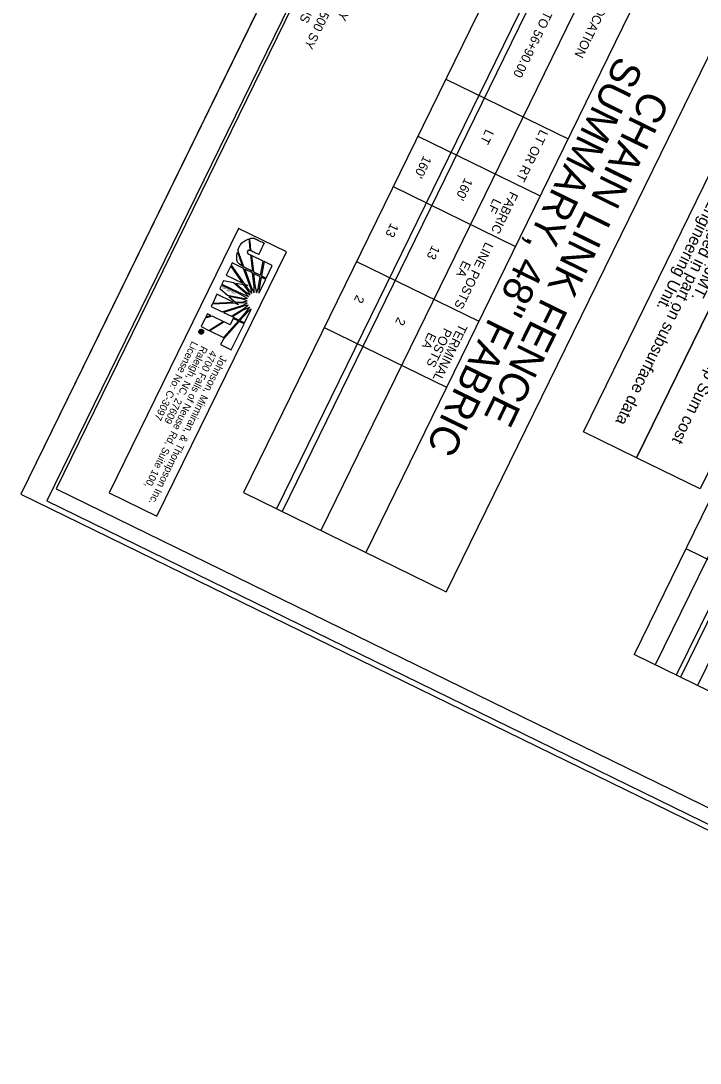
# Model space of a CAD drawing. Extents: x 1527431 to 1570373, y 611106 to 634616.
# Drawn here: x 1527567.8 to 1527683.1, y 634217 to 634394 of the extents above; entities that cross this region are included whole.
import ezdxf

# ---------------------------------------------------------------- set-up
doc = ezdxf.new("R2010")
doc.units = 0
for name, color, linetype in [('Sheet Cutting Line CELL', 7, 'Continuous'), ('Sheet Plot Border Inside CELL', 7, 'Continuous'), ('Sheet Plot Border Outside CELL', 7, 'Continuous'), ('Sheet Summary Earthwork CELL', 7, 'Continuous')]:
    doc.layers.add(name, color=color, linetype=linetype)

msp = doc.modelspace()

# ---------------------------------------------------------------- linework, layer by layer
at = {"layer": 'Sheet Cutting Line CELL'}
msp.add_line((1527715.73, 634616.24), (1527567.76, 634313.68), dxfattribs=at)
at = {"layer": 'Sheet Plot Border Inside CELL'}
msp.add_lwpolyline([(1527761.75, 634219.81), (1527908.19, 634519.22), (1527718.63, 634611.93), (1527572.19, 634312.52)], close=True, dxfattribs=at)
at = {"layer": 'Sheet Plot Border Outside CELL'}
msp.add_lwpolyline([(1527765.39, 634217.03), (1527913.36, 634519.58), (1527715.73, 634616.24), (1527567.76, 634313.68)], close=True, dxfattribs=at)
at = {"layer": 'Sheet Summary Earthwork CELL'}
for p, q in [((1527655.39, 634415.88), (1527605.53, 634313.93)), ((1527661.01, 634413.13), (1527611.14, 634311.18)), ((1527661.96, 634412.66), (1527612.1, 634310.71)), ((1527668.52, 634409.46), (1527618.66, 634307.51)), ((1527676.16, 634405.72), (1527626.3, 634303.77)), ((1527689.83, 634399.03), (1527639.97, 634297.08)), ((1527721.7, 634388.4), (1527671.84, 634286.45)), ((1527725.29, 634386.64), (1527675.43, 634284.69)), ((1527639.87, 634384.15), (1527660.64, 634373.99)), ((1527728.89, 634384.88), (1527679.02, 634282.93)), ((1527729.58, 634384.55), (1527679.72, 634282.59)), ((1527732.48, 634383.13), (1527682.62, 634281.18)), ((1527635.13, 634374.45), (1527655.9, 634364.29)), ((1527630.94, 634365.88), (1527651.71, 634355.72)), ((1527606.92, 634354.18), (1527607.23, 634351.42)), ((1527608.89, 634353.22), (1527606.92, 634354.18)), ((1527603.39, 634352.4), (1527602.62, 634350.83)), ((1527605.43, 634349.47), (1527603.39, 634352.4)), ((1527603.64, 634352.91), (1527603.47, 634352.56)), ((1527603.47, 634352.56), (1527605.73, 634349.33)), ((1527605.55, 634351.98), (1527603.64, 634352.91)), ((1527606.83, 634348.49), (1527605.55, 634351.98)), ((1527608.45, 634350.83), (1527608.89, 634353.22)), ((1527609.05, 634353.14), (1527608.6, 634350.75)), ((1527610.44, 634352.46), (1527609.05, 634353.14)), ((1527609.41, 634350.36), (1527610.44, 634352.46)), ((1527624.73, 634353.18), (1527645.5, 634343.02)), ((1527602.62, 634350.83), (1527605.43, 634349.47)), ((1527607.08, 634351.23), (1527605.77, 634351.87)), ((1527605.77, 634351.87), (1527606.99, 634348.52)), ((1527607.35, 634348.84), (1527607.08, 634351.23)), ((1527607.23, 634351.42), (1527608.45, 634350.83)), ((1527608.4, 634350.58), (1527607.26, 634351.14)), ((1527607.26, 634351.14), (1527607.49, 634349.07)), ((1527608.03, 634348.58), (1527608.4, 634350.58)), ((1527608.56, 634350.5), (1527608.19, 634348.5)), ((1527609.32, 634350.13), (1527608.56, 634350.5)), ((1527608.6, 634350.75), (1527609.41, 634350.36)), ((1527601.81, 634349.15), (1527601.53, 634348.56)), ((1527601.53, 634348.56), (1527602.81, 634347.43)), ((1527604.62, 634347.78), (1527601.81, 634349.15)), ((1527602.17, 634349.87), (1527601.89, 634349.3)), ((1527601.89, 634349.3), (1527604.69, 634347.93)), ((1527603.88, 634349.53), (1527602.17, 634349.87)), ((1527605.86, 634347.82), (1527603.88, 634349.53)), ((1527605.63, 634349.18), (1527604.2, 634349.45)), ((1527604.2, 634349.45), (1527606.04, 634347.89)), ((1527606.33, 634348.19), (1527605.63, 634349.18)), ((1527605.73, 634349.33), (1527606.29, 634349.06)), ((1527606.29, 634349.06), (1527605.86, 634349.14)), ((1527605.86, 634349.14), (1527606.44, 634348.31)), ((1527606.99, 634347.72), (1527606.83, 634348.49)), ((1527606.99, 634348.52), (1527607.36, 634347.84)), ((1527607.36, 634347.84), (1527607.35, 634348.84)), ((1527607.49, 634349.07), (1527607.78, 634347.85)), ((1527607.78, 634347.85), (1527608.03, 634348.58)), ((1527608.16, 634347.77), (1527609.32, 634350.13)), ((1527608.19, 634348.5), (1527608.16, 634347.77)), ((1527601.05, 634347.59), (1527600.32, 634346.08)), ((1527603.79, 634346.25), (1527601.05, 634347.59)), ((1527602.81, 634347.43), (1527605.42, 634346.91)), ((1527605.45, 634346.74), (1527603.06, 634347.23)), ((1527603.06, 634347.23), (1527604.17, 634346.27)), ((1527606.23, 634346.86), (1527604.62, 634347.78)), ((1527604.69, 634347.93), (1527606.39, 634347.21)), ((1527605.42, 634346.91), (1527606.23, 634346.86)), ((1527606.15, 634346.48), (1527605.45, 634346.74)), ((1527606.39, 634347.21), (1527605.86, 634347.82)), ((1527606.04, 634347.89), (1527606.66, 634347.51)), ((1527606.66, 634347.51), (1527606.33, 634348.19)), ((1527606.44, 634348.31), (1527606.99, 634347.72)), ((1527600.22, 634345.91), (1527600.04, 634345.54)), ((1527600.04, 634345.54), (1527601.93, 634344.62)), ((1527604.09, 634346.11), (1527600.22, 634345.91)), ((1527600.32, 634346.08), (1527603.79, 634346.25)), ((1527601.93, 634344.62), (1527605.49, 634345.74)), ((1527605.55, 634345.6), (1527602.15, 634344.51)), ((1527603.5, 634343.86), (1527605.53, 634345.1)), ((1527604.71, 634345.81), (1527604.09, 634346.11)), ((1527604.17, 634346.27), (1527605.42, 634346.33)), ((1527605.4, 634346.16), (1527604.34, 634346.12)), ((1527604.34, 634346.12), (1527604.71, 634345.81)), ((1527606.2, 634346.09), (1527605.4, 634346.16)), ((1527606.57, 634345.38), (1527605.41, 634344.85)), ((1527605.42, 634346.33), (1527606.15, 634346.48)), ((1527605.49, 634345.74), (1527606.2, 634346.09)), ((1527605.53, 634345.1), (1527606.33, 634345.72)), ((1527606.33, 634345.72), (1527605.55, 634345.6)), ((1527605.71, 634342.76), (1527606.86, 634345.09)), ((1527606.17, 634344.77), (1527606.57, 634345.38)), ((1527606.86, 634345.09), (1527606.29, 634344.63)), ((1527599.06, 634343.53), (1527598.37, 634342.11)), ((1527600.22, 634343.9), (1527599.06, 634343.53)), ((1527599.43, 634344.29), (1527599.16, 634343.74)), ((1527599.16, 634343.74), (1527600.02, 634344)), ((1527600.02, 634344), (1527599.43, 634344.29)), ((1527602.11, 634342.98), (1527600.22, 634343.9)), ((1527602.15, 634344.51), (1527603.5, 634343.86)), ((1527603.82, 634343.48), (1527603.29, 634342.4)), ((1527605.41, 634344.85), (1527603.68, 634343.77)), ((1527603.68, 634343.77), (1527604.79, 634343.21)), ((1527604.66, 634343.07), (1527603.82, 634343.48)), ((1527604.79, 634343.21), (1527606.17, 634344.77)), ((1527606.29, 634344.63), (1527604.95, 634343.13)), ((1527604.95, 634343.13), (1527605.71, 634342.76)), ((1527598.1, 634341.38), (1527598.03, 634341.42)), ((1527598.03, 634341.42), (1527598.03, 634341.42)), ((1527598.03, 634341.42), (1527598.1, 634341.38)), ((1527598.1, 634341.38), (1527598.1, 634341.38)), ((1527598.26, 634341.38), (1527598.29, 634341.46)), ((1527598.38, 634341.32), (1527598.26, 634341.38)), ((1527598.29, 634341.46), (1527598.62, 634341.3)), ((1527598.37, 634342.11), (1527599.67, 634341.47)), ((1527599.67, 634341.47), (1527602.11, 634342.98)), ((1527602.28, 634342.9), (1527599.83, 634341.39)), ((1527599.83, 634341.39), (1527602.16, 634340.26)), ((1527604.8, 634343), (1527602.13, 634340)), ((1527602.16, 634340.26), (1527604.68, 634343.06)), ((1527603.29, 634342.4), (1527602.28, 634342.9)), ((1527603.48, 634338.17), (1527605.64, 634342.59)), ((1527604.68, 634343.06), (1527604.66, 634343.07)), ((1527604.83, 634342.99), (1527604.8, 634343)), ((1527605.64, 634342.59), (1527604.83, 634342.99)), ((1527619.25, 634341.98), (1527640.02, 634331.82)), ((1527598.35, 634341.26), (1527598.36, 634341.26)), ((1527598.36, 634341.26), (1527598.38, 634341.32)), ((1527598.41, 634341.23), (1527598.36, 634341.26)), ((1527598.36, 634341.26), (1527598.41, 634341.23)), ((1527598.44, 634341.29), (1527598.41, 634341.23)), ((1527598.41, 634341.23), (1527598.41, 634341.23)), ((1527598.52, 634341.26), (1527598.44, 634341.29)), ((1527598.49, 634341.2), (1527598.52, 634341.26)), ((1527598.55, 634341.17), (1527598.49, 634341.2)), ((1527598.49, 634341.19), (1527598.49, 634341.2)), ((1527598.49, 634341.2), (1527598.55, 634341.17)), ((1527598.55, 634341.17), (1527598.54, 634341.15)), ((1527598.62, 634341.3), (1527598.55, 634341.17)), ((1527598.74, 634341.07), (1527598.67, 634341.11)), ((1527598.67, 634341.11), (1527598.74, 634341.07)), ((1527602.13, 634340), (1527601.67, 634339.06)), ((1527601.67, 634339.06), (1527603.48, 634338.17)), ((1527605.53, 634313.93), (1527639.97, 634297.08))]:
    msp.add_line(p, q, dxfattribs=at)
for points in [[(1527762.39, 634222.28), (1527894.2, 634491.77), (1527705.55, 634584.04), (1527573.75, 634314.54)], [(1527713.27, 634403.66), (1527672.28, 634319.84), (1527663.24, 634324.26), (1527704.23, 634408.08)], [(1527724.07, 634398.38), (1527683.07, 634314.56), (1527672.28, 634319.84), (1527713.27, 634403.66)], [(1527604.72, 634358.78), (1527582.75, 634313.86), (1527590.85, 634309.89), (1527612.83, 634354.82)]]:
    msp.add_lwpolyline(points, close=True, dxfattribs=at)
for points in [[(1527606.92, 634354.18), (1527607.23, 634351.42), (1527608.45, 634350.83), (1527608.89, 634353.22), (1527606.92, 634354.18)], [(1527603.39, 634352.4), (1527602.62, 634350.83), (1527605.43, 634349.47), (1527603.39, 634352.4)], [(1527606.99, 634347.72), (1527606.83, 634348.49), (1527605.55, 634351.98), (1527603.64, 634352.91), (1527603.47, 634352.56), (1527605.73, 634349.33), (1527606.29, 634349.06), (1527605.86, 634349.14), (1527606.44, 634348.31), (1527606.99, 634347.72)], [(1527609.05, 634353.14), (1527608.6, 634350.75), (1527609.41, 634350.36), (1527610.44, 634352.46), (1527609.05, 634353.14)], [(1527607.08, 634351.23), (1527605.77, 634351.87), (1527606.99, 634348.52), (1527607.36, 634347.84), (1527607.35, 634348.84), (1527607.08, 634351.23)], [(1527608.4, 634350.58), (1527607.26, 634351.14), (1527607.49, 634349.07), (1527607.78, 634347.85), (1527608.03, 634348.58), (1527608.4, 634350.58)], [(1527608.19, 634348.5), (1527608.16, 634347.77), (1527609.32, 634350.13), (1527608.56, 634350.5), (1527608.19, 634348.5)], [(1527606.23, 634346.86), (1527604.62, 634347.78), (1527601.81, 634349.15), (1527601.53, 634348.56), (1527602.81, 634347.43), (1527605.42, 634346.91), (1527606.23, 634346.86)], [(1527605.86, 634347.82), (1527603.88, 634349.53), (1527602.17, 634349.87), (1527601.89, 634349.3), (1527604.69, 634347.93), (1527606.39, 634347.21), (1527605.86, 634347.82)], [(1527606.66, 634347.51), (1527606.33, 634348.19), (1527605.63, 634349.18), (1527604.2, 634349.45), (1527606.04, 634347.89), (1527606.66, 634347.51)], [(1527601.05, 634347.59), (1527600.32, 634346.08), (1527603.79, 634346.25), (1527601.05, 634347.59)], [(1527606.15, 634346.48), (1527605.45, 634346.74), (1527603.06, 634347.23), (1527604.17, 634346.27), (1527605.42, 634346.33), (1527606.15, 634346.48)], [(1527606.2, 634346.09), (1527605.4, 634346.16), (1527604.34, 634346.12), (1527604.71, 634345.81), (1527604.09, 634346.11), (1527600.22, 634345.91), (1527600.04, 634345.54), (1527601.93, 634344.62), (1527605.49, 634345.74), (1527606.2, 634346.09)], [(1527606.33, 634345.72), (1527605.55, 634345.6), (1527602.15, 634344.51), (1527603.5, 634343.86), (1527605.53, 634345.1), (1527606.33, 634345.72)], [(1527606.57, 634345.38), (1527605.41, 634344.85), (1527603.68, 634343.77), (1527604.79, 634343.21), (1527606.17, 634344.77), (1527606.57, 634345.38)], [(1527606.29, 634344.63), (1527604.95, 634343.13), (1527605.71, 634342.76), (1527606.86, 634345.09), (1527606.29, 634344.63)], [(1527602.11, 634342.98), (1527600.22, 634343.9), (1527599.06, 634343.53), (1527598.37, 634342.11), (1527599.67, 634341.47), (1527602.11, 634342.98), (1527602.11, 634342.98)], [(1527599.43, 634344.29), (1527599.43, 634344.29), (1527599.16, 634343.74), (1527600.02, 634344), (1527599.43, 634344.29)], [(1527604.68, 634343.06), (1527604.66, 634343.07), (1527603.82, 634343.48), (1527603.29, 634342.4), (1527602.28, 634342.9), (1527599.83, 634341.39), (1527602.16, 634340.26), (1527604.68, 634343.06)], [(1527603.48, 634338.17), (1527605.64, 634342.59), (1527604.83, 634342.99), (1527604.8, 634343), (1527602.13, 634340), (1527601.67, 634339.06), (1527603.48, 634338.17)], [(1527598.24, 634341.15), (1527598.22, 634341.15), (1527598.21, 634341.16), (1527598.2, 634341.16), (1527598.16, 634341.17), (1527598.19, 634341.24)], [(1527680.63, 634304.41), (1527744.41, 634273.22), (1527735.62, 634255.25), (1527671.84, 634286.45)]]:
    msp.add_lwpolyline(points, dxfattribs=at)
for points, degree in [([(1527606.22, 634354.89), (1527606.28, 634355.02), (1527606.4, 634355.09), (1527606.66, 634355.02), (1527606.66, 634355.02), (1527606.46, 634356.99), (1527606.46, 634356.99), (1527605.75, 634356.76), (1527605.09, 634356.16), (1527604.79, 634355.53), (1527604.71, 634355.37), (1527604.66, 634355.24), (1527604.61, 634355.05), (1527604.61, 634355.05), (1527605.64, 634352.2), (1527605.64, 634352.2), (1527605.64, 634352.2), (1527607.06, 634351.51), (1527607.06, 634351.51), (1527607.06, 634351.51), (1527606.75, 634354.26), (1527606.75, 634354.26), (1527606.22, 634354.52), (1527606.14, 634354.72), (1527606.22, 634354.89)], 3), ([(1527606.22, 634354.89), (1527606.28, 634355.02), (1527606.4, 634355.09), (1527606.66, 634355.02), (1527606.66, 634355.02), (1527606.46, 634356.99), (1527606.46, 634356.99), (1527605.75, 634356.76), (1527605.09, 634356.16), (1527604.79, 634355.53), (1527604.71, 634355.37), (1527604.66, 634355.24), (1527604.61, 634355.05), (1527604.61, 634355.05), (1527605.64, 634352.2), (1527605.64, 634352.2), (1527605.64, 634352.2), (1527607.06, 634351.51), (1527607.06, 634351.51), (1527607.06, 634351.51), (1527606.75, 634354.26), (1527606.75, 634354.26), (1527606.22, 634354.52), (1527606.14, 634354.72), (1527606.22, 634354.89)], 3), ([(1527608.12, 634354.34), (1527608.12, 634354.34), (1527609.07, 634356.29), (1527609.07, 634356.29), (1527609.07, 634356.29), (1527607.85, 634356.88), (1527607.85, 634356.88), (1527607.85, 634356.88), (1527607.72, 634356.95), (1527607.72, 634356.95), (1527607.34, 634357.13), (1527606.98, 634357.15), (1527606.62, 634357.06), (1527606.62, 634357.06), (1527606.81, 634354.98), (1527606.83, 634354.97), (1527606.83, 634354.97), (1527608.12, 634354.34), (1527608.12, 634354.34)], 3), ([(1527605.42, 634352.31), (1527605.42, 634352.31), (1527604.53, 634354.77), (1527604.53, 634354.77), (1527604.33, 634353.87), (1527604.48, 634352.82), (1527605.42, 634352.31)], 3), ([(1527598.22, 634340.89), (1527598.12, 634340.93), (1527598.05, 634341.01), (1527598.01, 634341.11), (1527597.98, 634341.22), (1527597.98, 634341.32), (1527598.03, 634341.42)], 3), ([(1527598.03, 634341.42), (1527598.08, 634341.52), (1527598.16, 634341.58), (1527598.26, 634341.62), (1527598.36, 634341.66), (1527598.47, 634341.65), (1527598.57, 634341.6), (1527598.66, 634341.55), (1527598.73, 634341.48), (1527598.76, 634341.38), (1527598.8, 634341.27), (1527598.79, 634341.17), (1527598.74, 634341.07)], 3), ([(1527598.1, 634341.38), (1527598.06, 634341.3), (1527598.06, 634341.22), (1527598.09, 634341.14), (1527598.12, 634341.06), (1527598.17, 634340.99), (1527598.25, 634340.96), (1527598.33, 634340.92), (1527598.41, 634340.91), (1527598.5, 634340.94), (1527598.58, 634340.97), (1527598.63, 634341.03), (1527598.67, 634341.11)], 3), ([(1527598.67, 634341.11), (1527598.71, 634341.19), (1527598.72, 634341.27), (1527598.69, 634341.35), (1527598.67, 634341.43), (1527598.61, 634341.49), (1527598.53, 634341.53), (1527598.45, 634341.57), (1527598.37, 634341.58), (1527598.28, 634341.55), (1527598.2, 634341.52), (1527598.14, 634341.46), (1527598.1, 634341.38)], 3), ([(1527598.19, 634341.24), (1527598.21, 634341.24), (1527598.23, 634341.24), (1527598.25, 634341.23), (1527598.28, 634341.21), (1527598.3, 634341.21), (1527598.32, 634341.21)], 3), ([(1527598.74, 634341.07), (1527598.69, 634340.97), (1527598.62, 634340.91), (1527598.52, 634340.87), (1527598.42, 634340.83), (1527598.32, 634340.84), (1527598.22, 634340.89)], 3), ([(1527598.33, 634341.14), (1527598.31, 634341.13), (1527598.28, 634341.13), (1527598.24, 634341.15)], 2), ([(1527598.32, 634341.21), (1527598.33, 634341.22), (1527598.34, 634341.23), (1527598.35, 634341.26)], 2), ([(1527598.54, 634341.15), (1527598.5, 634341.06), (1527598.45, 634341.04), (1527598.39, 634341.07), (1527598.36, 634341.08), (1527598.34, 634341.11), (1527598.33, 634341.14)], 3), ([(1527598.41, 634341.23), (1527598.39, 634341.18), (1527598.39, 634341.15), (1527598.42, 634341.14), (1527598.44, 634341.13), (1527598.46, 634341.14), (1527598.49, 634341.19)], 3)]:
    msp.add_open_spline(points, degree=degree, dxfattribs=at)

# ---------------------------------------------------------------- texts
for s, height, rotation, p in [('CLASS IV SUBGRADE STABILIZATION - 1000 TONS', 1.55, 243.9377, (1527637.06, 634439.27)), ('GEOTEXTILE FOR SUBGRADE STABILIZATION - 1500 SY', 1.55, 243.9377, (1527640.34, 634439.9)), ('GEOTEXTILE FOR SOIL STABILIZATION - 2000 SY', 1.55, 243.9377, (1527642.92, 634438.5)), ('-L- Sta. 55+30.00 TO 56+90.00', 1.55, 243.9377, (1527663.94, 634410.75)), ('LOCATION', 1.55, 243.9377, (1527666.34, 634397.74)), ('provided by the Geotechnical Engineering Unit.', 2, 243.9377, (1527700.16, 634395.62)), ('These earthwork quantities are based in part on subsurface data ', 2, 243.9377, (1527702.23, 634394.61)), ('Earthwork quantities are calculated by JMT. ', 2, 243.9377, (1527704.3, 634393.6)), ('Asphalt Pavement will be paid for at the contract Lump Sum cost ', 2, 243.9377, (1527711.87, 634391.54)), ('SUMMARY, 48" FABRIC', 5, 243.9377, (1527669.05, 634388.29)), ('CHAIN LINK FENCE ', 5, 243.9377, (1527673.54, 634382.55)), ('LT', 1.55, 243.9377, (1527646.72, 634375.72)), ('LT OR RT', 1.55, 243.9377, (1527655.93, 634375.68)), ("160'", 1.55, 243.9377, (1527636.15, 634371.25)), ("160'", 1.55, 243.9377, (1527643.15, 634367.48)), ('FABRIC', 1.55, 243.9377, (1527650.85, 634365.17)), ('LF', 1.55, 243.9377, (1527648.01, 634363.98)), ('13', 1.55, 243.9377, (1527630.59, 634359.81)), ('13', 1.55, 243.9377, (1527637.6, 634356.04)), ('LINE POSTS', 1.55, 243.9377, (1527646.64, 634356.57)), ('EA', 1.55, 243.9377, (1527642.84, 634353.43)), ('www.jmt.com', 0.3103, 153.9377, (1527604.26, 634347.78)), ('2', 1.55, 243.9377, (1527624.76, 634347.6)), ('2', 1.55, 243.9377, (1527631.76, 634343.82)), ('POSTS', 1.55, 243.9377, (1527639.62, 634341.99)), ('TERMINAL', 1.55, 243.9377, (1527642.22, 634342.7)), ('License No: C-3097', 1.2413, 243.9377, (1527596.83, 634339.72)), ('EA', 1.55, 243.9377, (1527636.98, 634341.24)), ('4700 Falls of Neuse Rd, Suite 100, ', 1.2413, 243.9377, (1527600.02, 634338.16)), ('Raleigh, NC, 27609', 1.2413, 243.9377, (1527598.42, 634338.94)), ('Johnson, Mirmiran, & Thompson Inc.', 1.2778, 243.9377, (1527601.7, 634337.33))]:
    msp.add_text(s, height=height, rotation=rotation, dxfattribs=at).set_placement(p)

doc.saveas('drawing.dxf')
